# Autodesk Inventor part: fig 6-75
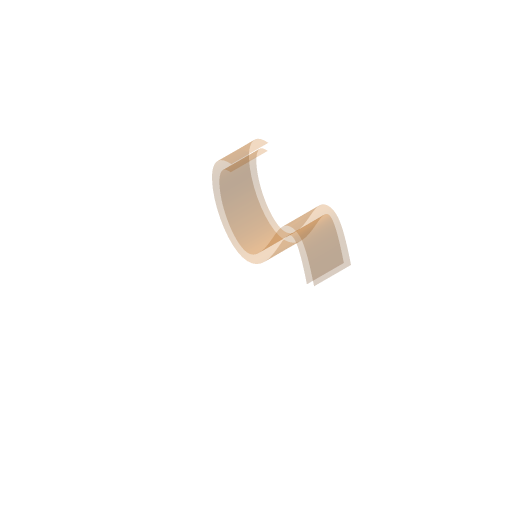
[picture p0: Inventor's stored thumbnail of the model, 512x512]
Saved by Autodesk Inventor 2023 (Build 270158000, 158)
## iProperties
Part Number: fig 6-75
Document SubType Name: Modeling
Created: 2002-12
Designer: deepak
Density: 1 g/cm^3
Material: Generic
Appearance: Default
Control State: 0
Master: False
Checked Out: False
Shininess: 64.0
Length Units: 11269
Angle Units: 11279
Time Units: 11290
Mass Units: 11283
Length Display Precision: 3
Angle Display Precision: 2
Compacted: True
Density: 0.0
Volumn: 0.0
Area: 0.0
PropertySet Name: Model Information
Author: deepak
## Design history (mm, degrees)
sketch "Sketch1"
  geometry: 5 further points
  constraints: 5 other
extrude_surface "ExtrusionSrf1" sketch "Sketch1" dims "d0" = 20, "d1" = 0
feature "OffsetSrf2" dims "d8" = 4, "d9" = 4
body "Solid1"
body "Srf1"
body "Srf2"
